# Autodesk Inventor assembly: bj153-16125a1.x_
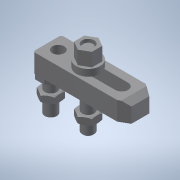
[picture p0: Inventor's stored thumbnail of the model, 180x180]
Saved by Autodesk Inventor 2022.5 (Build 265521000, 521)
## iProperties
Part Number: bj153-16125a1.x_
Material: 一般
Document SubType Name: Assembly
Designer: ImaoCorp
Sending System: SOLIDWORKS 2017-2017317
MC: AMD64
MC_MODEL: Intel64 Family 6 Model 60 Stepping 3, GenuineIntel
OS: Windows_NT
FRU: Parasolid Version 29.0, build 201,  4-17-2017
FORMAT: text
GUISE: transmit
KEY: bj153-16125a1
FILE: bj153-16125a1.x_t
DATE: Fri Mar 15 10:23:23 2019
Author: ImaoCorp
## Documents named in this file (7)
- X:\14_SW2022-Inv2022\00_全2023-1023新製品(TCC)まで\b\bj153-16125a1\BJ153-16125A1.iam
- X:\14_SW2022-Inv2022\00_全2023-1023新製品(TCC)まで\b\bj153-16125a1\bj153-16125a1_01.ipt
- X:\14_SW2022-Inv2022\00_全2023-1023新製品(TCC)まで\b\bj153-16125a1\bj153-16125a1_02.ipt
- X:\14_SW2022-Inv2022\00_全2023-1023新製品(TCC)まで\b\bj153-16125a1\bj153-16125a1_03.ipt
- X:\14_SW2022-Inv2022\00_全2023-1023新製品(TCC)まで\b\bj153-16125a1\bj153-16125a1_04.ipt
- X:\14_SW2022-Inv2022\00_全2023-1023新製品(TCC)まで\b\bj153-16125a1\bj153-16125a1_05.ipt
- X:\14_SW2022-Inv2022\00_全2023-1023新製品(TCC)まで\b\bj153-16125a1\bj153-16125a1_06.ipt
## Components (6 placed, 6 different names)
1. bj153-16125a1_01
2. bj153-16125a1_02
3. bj153-16125a1_03
4. bj153-16125a1_04
5. bj153-16125a1_05
6. bj153-16125a1_06
